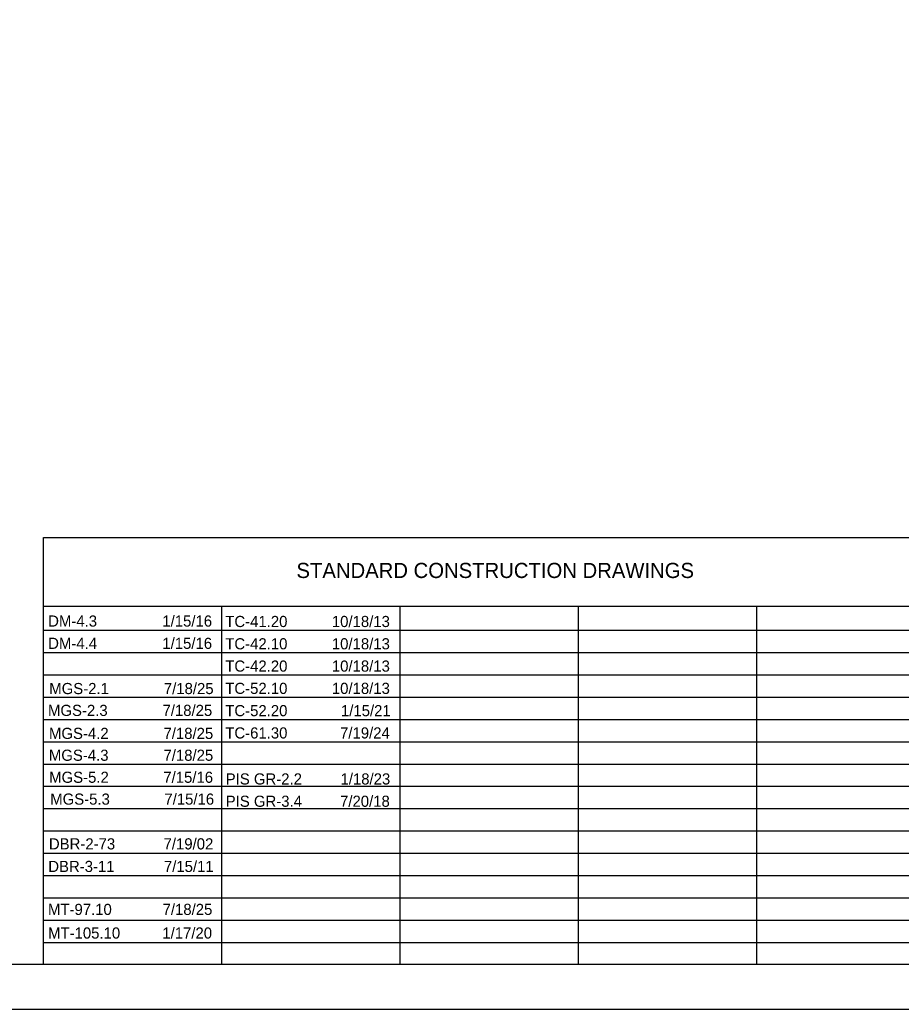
# Model space of a CAD drawing. Extents: x 0 to 34, y 0 to 22.
# Drawn here: x 9.88 to 19.77, y 0 to 11.1 of the extents above; entities that cross this region are included whole.
import ezdxf

# ---------------------------------------------------------------- set-up
doc = ezdxf.new("R2010")
doc.units = 0
for name, color, linetype in [('Default', 7, 'Continuous'), ('SH_Border', 7, 'Continuous'), ('SH_Cut_Line', 7, 'Continuous'), ('SH_Data', 7, 'Continuous'), ('SH_Text', 7, 'Continuous')]:
    doc.layers.add(name, color=color, linetype=linetype)

msp = doc.modelspace()

# ---------------------------------------------------------------- linework, layer by layer
at = {"layer": 'SH_Border'}
msp.add_lwpolyline([(1.5, 21.5), (33.5, 21.5), (33.5, 0.5), (1.5, 0.5)], close=True, dxfattribs=at)
at = {"layer": 'SH_Cut_Line'}
msp.add_lwpolyline([(0, 0), (34, 0), (34, 22), (0, 22)], close=True, dxfattribs=at)
at = {"layer": 'SH_Data'}
for p, q in [((10.15, 5.292), (23.6, 5.292)), ((10.15, 0.5), (10.15, 5.292)), ((10.15, 4.521), (23.6, 4.521)), ((12.15, 0.5), (12.15, 4.521)), ((14.15, 0.5), (14.15, 4.521)), ((16.15, 0.5), (16.15, 4.521)), ((18.15, 0.5), (18.15, 4.521)), ((10.15, 4.25), (23.6, 4.25)), ((10.15, 4), (23.6, 4)), ((10.15, 3.75), (23.6, 3.75)), ((10.15, 3.5), (23.6, 3.5)), ((10.15, 3.25), (23.6, 3.25)), ((10.15, 3), (23.6, 3)), ((10.15, 2.75), (23.6, 2.75)), ((10.15, 2.5), (23.6, 2.5)), ((10.15, 2.25), (23.6, 2.25)), ((10.15, 2), (23.6, 2)), ((10.15, 1.75), (23.6, 1.75)), ((10.15, 1.5), (23.6, 1.5)), ((10.15, 1.25), (23.6, 1.25)), ((10.15, 1), (23.6, 1)), ((10.15, 0.75), (23.6, 0.75))]:
    msp.add_line(p, q, dxfattribs=at)

# ---------------------------------------------------------------- texts
at = {"layer": 'Default'}
for s, p in [('DM-4.3', (10.202, 4.291)), ('1/15/16', (11.482, 4.291)), ('TC-41.20', (12.188, 4.286)), ('10/18/13', (13.383, 4.286)), ('DM-4.4', (10.202, 4.041)), ('1/15/16', (11.482, 4.041)), ('TC-42.10', (12.188, 4.036)), ('10/18/13', (13.383, 4.036)), ('TC-42.20', (12.188, 3.786)), ('10/18/13', (13.383, 3.786)), ('7/18/25', (11.499, 3.534)), ('TC-52.10', (12.188, 3.536)), ('10/18/13', (13.383, 3.536)), ('MGS-2.1', (10.214, 3.534)), ('MGS-2.3', (10.2, 3.289)), ('7/18/25', (11.484, 3.289)), ('TC-52.20', (12.188, 3.286)), ('1/15/21', (13.485, 3.286)), ('MGS-4.2', (10.211, 3.031)), ('7/18/25', (11.495, 3.031)), ('TC-61.30', (12.188, 3.036)), ('7/19/24', (13.475, 3.036)), ('MGS-4.3', (10.21, 2.786)), ('7/18/25', (11.495, 2.786)), ('MGS-5.2', (10.213, 2.539)), ('7/15/16', (11.493, 2.539)), ('PIS GR-2.2', (12.193, 2.52)), ('1/18/23', (13.48, 2.52)), ('MGS-5.3', (10.225, 2.294)), ('7/15/16', (11.505, 2.294)), ('PIS GR-3.4', (12.193, 2.27)), ('7/20/18', (13.475, 2.27)), ('DBR-2-73', (10.21, 1.792)), ('7/19/02', (11.496, 1.792)), ('DBR-3-11', (10.203, 1.539)), ('7/15/11', (11.5, 1.539)), ('MT-97.10', (10.2, 1.057)), ('7/18/25', (11.485, 1.057)), ('MT-105.10', (10.201, 0.792)), ('1/17/20', (11.482, 0.792))]:
    msp.add_text(s, height=0.125, dxfattribs=at).set_placement(p)
at = {"layer": 'SH_Text'}
msp.add_text('STANDARD CONSTRUCTION DRAWINGS', height=0.17, dxfattribs=at).set_placement((12.986, 4.836))

doc.saveas('drawing.dxf')
